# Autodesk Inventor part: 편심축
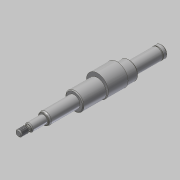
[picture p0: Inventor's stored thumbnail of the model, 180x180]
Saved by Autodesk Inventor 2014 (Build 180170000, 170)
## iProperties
Created: 2015-09
Part Number: 편심축
Material: 강철, 연강
Document SubType Name: Modeling
Designer: mduedu
Density: 1 g/cm^3
Appearance: 강철
Author: mduedu
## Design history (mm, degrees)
sketch "스케치1"
  geometry: L1 (-91, 0)-(91, 0); L2 (-91, 0)-(-91, 7.5); L3 (-91, 7.5)-(-49.85, 7.5); L4 (-49.85, 7.5)-(-49.85, 11.5); L5 (-49.85, 11.5)-(20.15, 11.5); L6 (20.15, 11.5)-(20.15, 7.5); L7 (20.15, 7.5)-(59.15, 7.5); L8 (59.15, 7.5)-(59.15, 5); L9 (59.15, 5)-(78.15, 5); L10 (78.15, 5)-(78.15, 3); L11 (78.15, 3)-(80.15, 3); L12 (81.882, 4)-(91, 4); L13 (91, 4)-(91, 0); L14 (80.15, 3)-(81.882, 4); 2 further points
  constraints: 28 end point, 9 parallel, 2 perpendicular, 1 coincident, 1 collinear, 1 horizontal, 1 midpoint
  dimensions: "d0" = 41.15 distance of L2.end L3.end; "d2" = 70 distance of L4.end L5.end; "d3" = 39 distance of L6.end L7.end; "d4" = 182 distance of L1.start L1.end; "d5" = 19 distance of L8.end L9.end; "d7" = 8 diameter of L12 L1; "d8" = 6 diameter of L11 L1; "d9" = 10 diameter of L9 L1; "d10" = 15 diameter of L7 L1; "d11" = 23 diameter of L5 L1; "d12" = 15 diameter of L3 L1; "d40" = 30 deg angle of L14 L12; "d41" = 2 distance of L10.end L11.end; "d42" = 3.73205 horizontal distance of L12.start L10.end (derived)
revolve "회전1" sketch "스케치1" stored, may be unused: angle "d13" = 90 deg
fillet "모깎기1" dims "d43" = 0.6
sketch "스케치2"
  geometry: L1 (-91, 7.5)-(-49.85, 7.5) reference; L2 (-91, -7.5)-(-91, 7.5) reference; L3 (91, -4)-(91, 4) reference; L4 (-91, 0)-(91, 0); L5 (-86, 7.5)-(-84.85, 7.5); L6 (-84.85, 7.5)-(-84.85, 7.15); L7 (-84.85, 7.15)-(-86, 7.15); L8 (-86, 7.15)-(-86, 7.5); 1 further point
  constraints: 10 end point, 2 midpoint, 2 parallel, 1 horizontal, 1 perpendicular, 1 point on line
  dimensions: "d14" = 5 distance between parallel lines of L8 L2; "d15" = 14.3 diameter of L7 L4; "d16" = 1.15 distance of L6.end L7.end
revolve "회전2" sketch "스케치2" stored, may be unused: angle "d17" = 90 deg
node "작업 평면1"
sketch "스케치3"
  geometry: C1 r 11.5 at (0, 0) reference; C2 r 14 at (0, 2.5); 1 further point
  constraints: 1 centre point, 1 tangent, 1 vertical alignment
  dimensions: "d19" = 28 diameter of C2
extrude "돌출1" join sketch "스케치3" distance "d21" = 25; taper "d22" = 0 deg
node "작업 평면2"
sketch "스케치4"
  geometry: L1 (9.5, 7.5)-(9.5, -7.5) reference; L2 (-9.5, 5)-(-9.5, -5) reference; L3 (9.5, 0)-(-9.5, 0); L4 (-5, -1.5)-(4, -1.5); L5 (4, 1.5)-(-5, 1.5); A1 r 1.5 centre (4, 0) between (4, -1.5) and (4, 1.5); A2 r 1.5 centre (-5, 0) between (-5, 1.5) and (-5, -1.5); 1 further point
  constraints: 6 end point, 4 point on circle, 4 tangent, 2 centre point, 2 midpoint, 2 parallel, 1 point on line
  dimensions: "d23" = 3 distance between parallel lines of L5 L4; "d25" = 12 dimension on A2 A1; "d26" = 3 distance edge to line of A2 L2
extrude "돌출2" cut sketch "스케치4" distance "d27" = 1.8; taper "d28" = 0 deg
chamfer "모따기1" distance "d29" = 1; stored, may be unused: second distance "d30" = 2, angle "d31" = 45 deg
sketch "스케치5"
  geometry: L1 (80.289, 3.08)-(81.882, 4) reference; L2 (81.882, 4)-(91, 4) reference; L3 (91, 4)-(91, -4) reference; L4 (91, -4)-(81.882, -4) reference; L5 (81.882, -4)-(80.289, -3.08) reference; L6 (79.989, -3)-(78.75, -3) reference; L7 (78.15, -3.6)-(78.15, -5) reference; L8 (78.15, -5)-(75.15, -5) reference; L9 (75.15, -5)-(75.15, -3.2) reference; L10 (75.15, -3.2)-(63.15, -3.2) reference; L11 (63.15, -3.2)-(63.15, -5) reference; L12 (63.15, -5)-(59.15, -5) reference; L13 (59.15, -5)-(59.15, -7.5) reference; L14 (59.15, -7.5)-(20.15, -7.5) reference; L15 (20.15, -7.5)-(20.15, -10.5) reference; L16 (20.15, -10.5)-(19.15, -11.5) reference; L17 (19.15, -11.5)-(-9.35, -11.5) reference; L18 (-9.35, -11.5)-(-34.35, -11.5) reference; L19 (-34.35, -11.5)-(-48.85, -11.5) reference; L20 (-48.85, -11.5)-(-49.85, -10.5) reference; L21 (-49.85, -10.5)-(-49.85, -7.5) reference; L22 (-49.85, -7.5)-(-84.85, -7.5) reference; L23 (-84.85, -7.5)-(-84.85, -7.15) reference; L24 (-84.85, -7.15)-(-86, -7.15) reference; L25 (-86, -7.15)-(-86, -7.5) reference; L26 (-86, -7.5)-(-90, -7.5) reference; L27 (-90, -7.5)-(-91, -6.5) reference; L28 (-91, -6.5)-(-91, 6.5) reference; L29 (-91, 6.5)-(-90, 7.5) reference; L30 (-90, 7.5)-(-86, 7.5) reference; L31 (-86, 7.5)-(-86, 7.15) reference; L32 (-86, 7.15)-(-84.85, 7.15) reference; L33 (-84.85, 7.15)-(-84.85, 7.5) reference; L34 (-84.85, 7.5)-(-49.85, 7.5) reference; L35 (-49.85, 7.5)-(-49.85, 10.5) reference; L36 (-49.85, 10.5)-(-48.85, 11.5) reference; L37 (-48.85, 11.5)-(-34.35, 11.5) reference; L38 (-34.35, 11.5)-(-34.35, 16.5) reference; L39 (-34.35, 16.5)-(-9.35, 16.5) reference; L40 (-9.35, 16.5)-(-9.35, 11.5) reference; L41 (-9.35, 11.5)-(19.15, 11.5) reference; L42 (19.15, 11.5)-(20.15, 10.5) reference; L43 (20.15, 10.5)-(20.15, 7.5) reference; L44 (20.15, 7.5)-(59.15, 7.5) reference; L45 (59.15, 7.5)-(59.15, 5) reference; L46 (59.15, 5)-(78.15, 5) reference; L47 (78.15, 5)-(78.15, 3.6) reference; L48 (78.75, 3)-(79.989, 3) reference; L49 (0, 0)-(91, 0); L50 (59.15, -6.55)-(57.505, -7.5); L51 (57.505, -7.5)-(59.15, -7.5); L52 (59.15, -7.5)-(59.15, -6.55); A1 r 0.6 centre (79.989, 3.6) between (79.989, 3) and (80.289, 3.08) reference; A2 r 0.6 centre (79.989, -3.6) between (80.289, -3.08) and (79.989, -3) reference; A3 r 0.6 centre (78.75, -3.6) between (78.75, -3) and (78.15, -3.6) reference; A4 r 0.6 centre (78.75, 3.6) between (78.15, 3.6) and (78.75, 3) reference
  constraints: 8 end point, 2 point on line, 1 midpoint, 1 parallel, 1 perpendicular
  dimensions: "d44" = 30 deg angle of L50 L51; "d45" = 13.1 diameter of L50.start L49
revolve "회전3" sketch "스케치5" stored, may be unused: angle "d46" = 90 deg
fillet "모깎기2" dims "d47" = 4, "d48" = 0.5
feature "스레드1" dims "d32" = 10, "d33" = 0
chamfer "모따기2" distance "d34" = 1; stored, may be unused: second distance "d35" = 2, angle "d36" = 45 deg
chamfer "모따기3" distance "d37" = 1; stored, may be unused: second distance "d38" = 2, angle "d39" = 45 deg
node "솔리드1"
node "절단 모서리 투영1"
other parameters: "d18" = -29.5
